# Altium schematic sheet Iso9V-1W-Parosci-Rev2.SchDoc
size Tabloid; Organization: Monterey Bay Aquarium Research Institute; Address1: 7700 Sandholdt Rd; Address2: Moss Landing, CA 95039-9644; CompanyName: MBARI
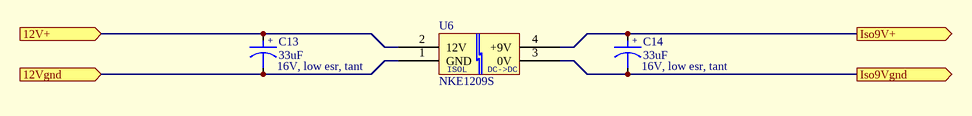
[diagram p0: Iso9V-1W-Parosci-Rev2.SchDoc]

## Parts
C13  33uF  DescSheet: 16V, low esr, tant  [6032pol]
C14  33uF  DescSheet: 16V, low esr, tant  [6032pol]
U6  NKE1209S  [NKEDCDC]

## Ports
12V+ (in), 12Vgnd (in), Iso9V+ (out), Iso9Vgnd (out)

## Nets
12V+: C13.1 U6.2(12V) ; port 12V+
12Vgnd: C13.2 U6.1(GND) ; port 12Vgnd
Iso9V+: C14.1 U6.4(+9V) ; port Iso9V+
Iso9Vgnd: C14.2 U6.3(0V) ; port Iso9Vgnd

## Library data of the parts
C13 C14 = CAPACITOR POL: Capacitor; ManufPartNo: EEJ-L1CC336R; Manufacturer: Panasonic; VendorPartNo: P11290CT-ND; Cost/ea: 1.057; Reference: T033, 718; Vendor: Digi-Key
U6 = NKE1209S: DC->DC Isol Converter 12->9VDC; Manufacturer: C&D Technologies; VendorPartNo: 580-NKE1209S; Cost/ea: 8.33; Reference: Cat616, 1032; Vendor: Mouser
